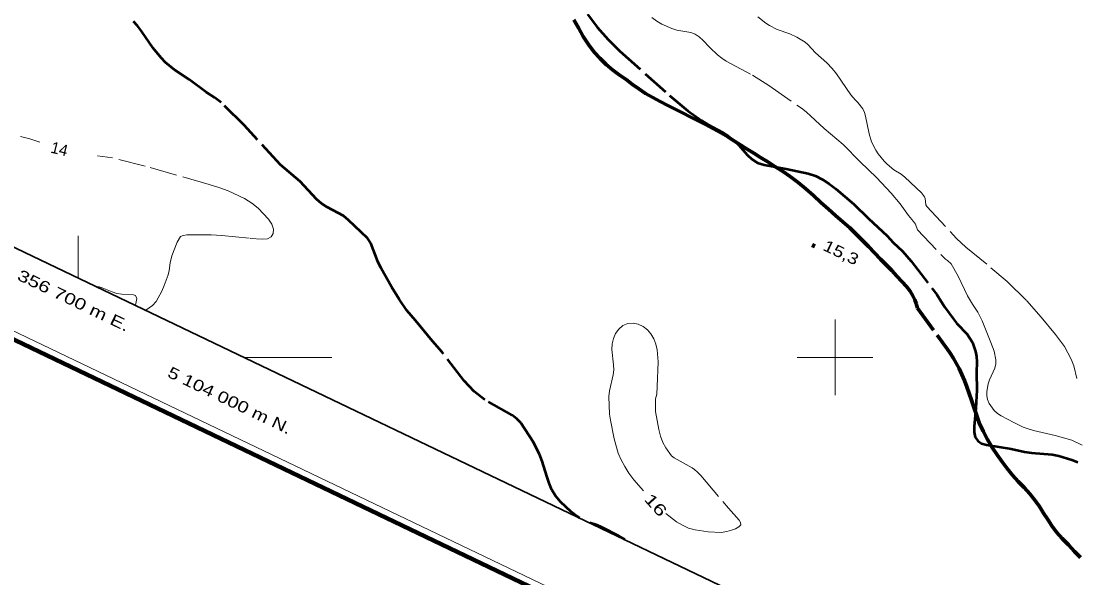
# Model space of a CAD drawing. Extents: x 355726 to 357533, y 5103782 to 5105258.
# Drawn here: x 356692.4 to 356831.8, y 5103970.9 to 5104044.4 of the extents above; entities that cross this region are included whole.
import ezdxf
from ezdxf.enums import TextEntityAlignment as Align

# ---------------------------------------------------------------- set-up
doc = ezdxf.new("R2010")
doc.units = 0
doc.header["$LTSCALE"] = 0.6
doc.linetypes.add('LONG_DASHED', pattern=[7.5, 6, -1.5])
for name, color, linetype, lineweight in [('1', 7, 'LONG_DASHED', 53), ('2', 7, 'LONG_DASHED', 13), ('22', 7, 'Continuous', 13), ('3', 7, 'Continuous', 140), ('60', 7, 'Continuous', 13), ('61', 7, 'Continuous', 13)]:
    doc.layers.add(name, color=color, linetype=linetype, lineweight=lineweight)

msp = doc.modelspace()

# ---------------------------------------------------------------- linework, layer by layer
at = {"layer": '1'}
for points in [[(356767.3, 5104045.33), (356768.57, 5104043.59), (356770.01, 5104041.99), (356771.56, 5104040.45), (356778.13, 5104034.59), (356780.54, 5104032.55), (356782.35, 5104031.29), (356783.27, 5104030.72), (356785.08, 5104029.72), (356785.9, 5104029.19), (356786.64, 5104028.62), (356787.29, 5104028.03), (356788.37, 5104026.75), (356788.98, 5104026.15), (356789.72, 5104025.69), (356790.63, 5104025.4), (356793.51, 5104024.91), (356796.44, 5104024.28), (356797.41, 5104023.97), (356798.33, 5104023.49), (356799.23, 5104022.9), (356800.09, 5104022.24), (356802.46, 5104020.21), (356804.41, 5104018.32), (356806.87, 5104016.03), (356807.67, 5104015.18), (356808.92, 5104014.01), (356810.05, 5104012.69), (356813.44, 5104008.28), (356814.45, 5104006.69), (356815.66, 5104005.01), (356816.08, 5104004.48), (356817.43, 5104003.05), (356818.16, 5104001.98), (356818.55, 5104000.76), (356818.66, 5104000.09), (356818.7, 5103999.42), (356818.66, 5103997.99), (356818.7, 5103995.65), (356818.61, 5103993.3), (356818.37, 5103990.88), (356818.35, 5103990.13), (356818.5, 5103989.47), (356818.84, 5103988.96), (356819.35, 5103988.63), (356820, 5103988.44), (356823.24, 5103987.9), (356825.02, 5103987.5), (356825.94, 5103987.37), (356828.67, 5103987.18), (356829.57, 5103986.99), (356831.27, 5103986.46), (356832.08, 5103986.16)], [(356766.22, 5103978.8), (356765.86, 5103979.01), (356765.14, 5103979.59), (356763.7, 5103980.94), (356763.06, 5103981.7), (356762.58, 5103982.49), (356762.21, 5103983.37), (356761.89, 5103984.3), (356761.31, 5103986.28), (356760.95, 5103987.21), (356760.12, 5103988.84), (356758.49, 5103991.33), (356757.95, 5103991.88), (356757.34, 5103992.37), (356753.72, 5103994.37), (356752.29, 5103995.5), (356750.97, 5103996.9), (356748.09, 5104000.67), (356746.8, 5104002.12), (356744.55, 5104004.87), (356743.41, 5104006.18), (356742.4, 5104007.67), (356741.38, 5104009.3), (356740.41, 5104011.01), (356739.96, 5104011.84), (356739.59, 5104012.67), (356738.65, 5104015.07), (356738.22, 5104015.75), (356735.69, 5104018.13), (356735.03, 5104018.67), (356732.87, 5104019.84), (356732.14, 5104020.33), (356731.48, 5104020.9), (356729.3, 5104023.21), (356726.72, 5104025.42), (356721.9, 5104030.67), (356718.86, 5104033.65), (356717.99, 5104034.3), (356716.9, 5104035.03), (356714.64, 5104036.71), (356712.71, 5104037.95), (356711.54, 5104038.95), (356710.96, 5104039.53), (356709.9, 5104040.84), (356708.37, 5104043.05), (356707.82, 5104043.78), (356707.3, 5104044.34)], [(356772.22, 5103975.93), (356771.38, 5103976.42), (356769.21, 5103977.55), (356768.55, 5103977.83), (356767.58, 5103978.15)]]:
    msp.add_lwpolyline(points, dxfattribs=at)
at = {"layer": '2'}
for points in [[(356775.79, 5104044.87), (356776.42, 5104044.38), (356777.1, 5104043.98), (356778.42, 5104043.41), (356779.08, 5104043.21)], [(356789.8, 5104044.98), (356790.83, 5104044.13), (356791.31, 5104043.8), (356792.33, 5104043.29), (356794.02, 5104042.73), (356794.92, 5104042.28), (356796.02, 5104041.61), (356796.37, 5104041.3), (356797.4, 5104040.21), (356798.92, 5104038.9), (356799.59, 5104038.16), (356800.16, 5104037.42), (356802.06, 5104034.66), (356802.63, 5104034.01), (356803, 5104033.67), (356803.66, 5104032.8), (356803.89, 5104032.32), (356804.03, 5104031.84), (356804.48, 5104029.51), (356804.81, 5104028.44), (356805.38, 5104027.36), (356805.7, 5104026.87), (356806.46, 5104025.91), (356806.86, 5104025.49), (356807.76, 5104024.78), (356808.72, 5104024.18), (356809.22, 5104023.8), (356811.42, 5104021.73), (356811.79, 5104021.21), (356811.89, 5104020.97), (356811.99, 5104020.13), (356812.12, 5104019.9), (356816.05, 5104015.7), (356817.26, 5104014.57), (356820.59, 5104011.84), (356822.71, 5104010), (356825.31, 5104007.46), (356827.22, 5104005.32), (356829.12, 5104003), (356830.3, 5104001.41), (356831.19, 5103999.75)], [(356779.08, 5104043.21), (356780.92, 5104042.91), (356781.49, 5104042.68), (356782.03, 5104042.34), (356782.53, 5104041.9), (356783.45, 5104040.92), (356784.46, 5104039.94), (356785.01, 5104039.5), (356785.62, 5104039.09), (356789.09, 5104037.25), (356791.24, 5104035.88), (356795.55, 5104032.9), (356796.18, 5104032.41), (356798.55, 5104030.24), (356801.04, 5104028.12), (356803.3, 5104025.8), (356805.47, 5104023.73), (356807.4, 5104021.66), (356808.59, 5104020.26), (356809.7, 5104018.71), (356810.37, 5104017.95), (356810.62, 5104017.57), (356810.88, 5104016.84), (356814.58, 5104012.96), (356814.84, 5104012.8), (356815.31, 5104012.36), (356816.24, 5104010.72), (356817.49, 5104008.13), (356818.13, 5104007.03), (356818.85, 5104005.95), (356819.44, 5104004.83), (356820.58, 5104001.95), (356820.99, 5104000.8), (356821.23, 5103999.69), (356821.23, 5103999.15), (356821.12, 5103998.59), (356820.38, 5103997.04), (356820.21, 5103996.51), (356820.03, 5103995.47), (356820.04, 5103994.92), (356820.15, 5103994.42), (356820.35, 5103993.91), (356821.03, 5103992.98), (356821.44, 5103992.59), (356821.92, 5103992.28), (356823.62, 5103991.38), (356824.86, 5103990.8), (356825.51, 5103990.55), (356826.19, 5103990.34), (356829.05, 5103989.66), (356831.26, 5103989.05), (356832.64, 5103988.41)], [(356694.91, 5104028.41), (356693.59, 5104028.84), (356692.38, 5104029.16)], [(356708.93, 5104006.22), (356709.82, 5104006.86), (356710.27, 5104007.38), (356711.02, 5104008.75), (356711.36, 5104009.5), (356711.86, 5104010.88), (356712.01, 5104011.46), (356712.16, 5104012.5), (356712.36, 5104013.41), (356713.06, 5104015.19), (356713.52, 5104015.94), (356713.86, 5104016.11), (356714.33, 5104016.18), (356717.56, 5104016.18), (356718.98, 5104016.11), (356722.71, 5104015.71), (356724.32, 5104015.61), (356725, 5104015.67), (356725.5, 5104015.93), (356725.76, 5104016.36), (356725.78, 5104016.94), (356725.56, 5104017.59), (356725.12, 5104018.24), (356723.75, 5104019.71), (356722.92, 5104020.38), (356721.98, 5104020.97), (356719.82, 5104021.99), (356718.58, 5104022.44), (356717.29, 5104022.84), (356708.83, 5104025.25), (356704.5, 5104026.36), (356702.56, 5104026.59)], [(356702.48, 5104009.3), (356702.74, 5104009.29), (356703.14, 5104009.19), (356704.47, 5104008.63), (356705.09, 5104008.44), (356705.76, 5104008.34), (356707.28, 5104008.24), (356707.55, 5104008.15), (356707.73, 5104007.76), (356707.55, 5104006.88)], [(356774.7, 5103982.37), (356773.42, 5103983.84), (356772.76, 5103984.71), (356772.2, 5103985.57), (356771.72, 5103986.46), (356771.33, 5103987.36), (356770.79, 5103989.23), (356770.3, 5103991.72), (356770.18, 5103992.5), (356770.12, 5103994.83), (356770.18, 5103995.59), (356770.66, 5103997.67), (356770.74, 5103998.34), (356770.73, 5103999.01), (356770.51, 5104001.05), (356770.56, 5104001.78), (356770.71, 5104002.5), (356770.99, 5104003.16), (356771.4, 5104003.74), (356771.94, 5104004.19), (356772.59, 5104004.45), (356773.31, 5104004.53), (356773.98, 5104004.4), (356774.62, 5104004.09), (356775.2, 5104003.65), (356775.66, 5104003.09), (356776.03, 5104002.45), (356776.3, 5104001.74), (356776.48, 5104000.98), (356776.6, 5103999.42), (356776.5, 5103996.13), (356776.42, 5103995.13), (356776.26, 5103994.51), (356776.27, 5103992.86), (356776.69, 5103990.46), (356776.94, 5103989.57), (356777.23, 5103988.76), (356777.61, 5103988.05), (356778.36, 5103987.01), (356778.72, 5103986.72), (356781.11, 5103985.4), (356781.43, 5103985.19), (356781.82, 5103984.84), (356782.26, 5103984.38), (356785.89, 5103980.08), (356787.3, 5103978.51), (356787.51, 5103978.2), (356787.53, 5103977.88), (356787.28, 5103977.63), (356786.84, 5103977.37), (356786.31, 5103977.16), (356785.67, 5103976.99), (356784.94, 5103976.88), (356783.24, 5103976.94), (356781.49, 5103977.21), (356780.62, 5103977.45), (356779.82, 5103977.82), (356779.04, 5103978.26), (356777.62, 5103979.38)], [(356831.19, 5103999.75), (356831.52, 5103998.86), (356831.95, 5103997.22)]]:
    msp.add_lwpolyline(points, dxfattribs=at)
at = {"layer": '22', "linetype": 'LONG_DASHED', "lineweight": 70}
for points in [[(356765.48, 5104044.59), (356766.09, 5104043.5), (356766.72, 5104042.37), (356767.4, 5104041.3), (356768.16, 5104040.3), (356768.94, 5104039.45), (356769.74, 5104038.68), (356770.57, 5104037.97), (356771.48, 5104037.3), (356772.37, 5104036.67), (356773.24, 5104036.03), (356774.08, 5104035.44), (356774.95, 5104034.84), (356775.9, 5104034.33), (356776.9, 5104033.78), (356777.91, 5104033.26), (356778.87, 5104032.76), (356779.85, 5104032.28), (356780.83, 5104031.78), (356781.83, 5104031.26), (356782.89, 5104030.74), (356783.93, 5104030.19), (356784.91, 5104029.65), (356785.84, 5104029.13), (356786.7, 5104028.55), (356787.52, 5104028.01), (356788.39, 5104027.51), (356789.26, 5104026.97), (356790.15, 5104026.4), (356791.09, 5104025.8), (356792.04, 5104025.2), (356793.05, 5104024.57), (356794.07, 5104023.86), (356795.1, 5104023.09), (356796.12, 5104022.26), (356797.12, 5104021.36), (356798.13, 5104020.46), (356799.11, 5104019.55), (356800.06, 5104018.71), (356801.01, 5104017.88), (356801.92, 5104017.08)], [(356801.92, 5104017.08), (356802.78, 5104016.26), (356803.62, 5104015.45), (356804.41, 5104014.63), (356805.2, 5104013.8), (356805.99, 5104012.97), (356806.76, 5104012.2), (356807.5, 5104011.47), (356808.17, 5104010.73), (356808.81, 5104010.03), (356809.42, 5104009.37), (356809.91, 5104008.73), (356810.25, 5104008.13), (356810.52, 5104007.59), (356810.7, 5104007.09), (356810.89, 5104006.51), (356813.48, 5104002.94), (356813.84, 5104002.46), (356814.08, 5104002.08), (356814.41, 5104001.63), (356814.8, 5104001.13), (356815.2, 5104000.55), (356815.6, 5103999.94), (356815.99, 5103999.25), (356816.38, 5103998.54), (356816.74, 5103997.75), (356817.08, 5103996.94), (356817.4, 5103996.09), (356817.71, 5103995.23), (356818.03, 5103994.34), (356818.32, 5103993.4), (356818.66, 5103992.42), (356819.05, 5103991.36), (356819.56, 5103990.25), (356820.12, 5103989.15), (356820.76, 5103988.11), (356821.4, 5103987.13), (356822.06, 5103986.21), (356822.72, 5103985.32), (356823.42, 5103984.46), (356824.16, 5103983.62), (356824.97, 5103982.8), (356825.71, 5103981.97), (356826.4, 5103981.13), (356826.99, 5103980.29), (356827.54, 5103979.44), (356828.08, 5103978.59), (356828.62, 5103977.75), (356829.26, 5103976.92), (356830.01, 5103976.08), (356830.82, 5103975.24), (356831.64, 5103974.38), (356832.41, 5103973.57)]]:
    msp.add_lwpolyline(points, dxfattribs=at)
at = {"layer": '3'}
msp.add_line((356796.97, 5104014.85), (356797.33, 5104014.68), dxfattribs=at)
at = {"layer": '60', "lineweight": 158}
msp.add_lwpolyline([(355725.74, 5104464.62), (357152.72, 5103781.6), (357532.66, 5104575.38), (356105.68, 5105258.4)], close=True, dxfattribs=at)
at = {"layer": '60'}
msp.add_lwpolyline([(355727.1, 5104465.08), (357152.24, 5103782.93), (357531.32, 5104574.91), (356106.18, 5105257.06)], close=True, dxfattribs=at)
at = {"layer": '60', "lineweight": 35}
msp.add_lwpolyline([(355740.43, 5104469.78), (356913.03, 5103908.53), (357283.46, 5104682.46), (356110.86, 5105243.71)], close=True, dxfattribs=at)
at = {"layer": '61'}
for p, q in [((356700, 5104010.49), (356700, 5104016.04)), ((356800, 5103995), (356800, 5104005)), ((356721.92, 5104000), (356733.51, 5104000)), ((356795, 5104000), (356805, 5104000))]:
    msp.add_line(p, q, dxfattribs=at)

# ---------------------------------------------------------------- texts
at = {"layer": '2'}
msp.add_text('14', height=1.5, rotation=346.104, dxfattribs=at).set_placement((356697.33, 5104026.79), align=Align.CENTER)
at = {"layer": '2', "width": 1.45}
msp.add_text('16', height=1.5, rotation=312.099, dxfattribs=at).set_placement((356775.74, 5103980), align=Align.CENTER)
at = {"layer": '3', "width": 1.25}
msp.add_text('15,3   ', height=1.5, rotation=334.423, dxfattribs=at).set_placement((356798.26, 5104014.22))
at = {"layer": '61'}
for s, width, p in [(' 356 700 m E.', 1.35, (356698.73, 5104006.99)), (' 5 104 000 m N.', 1.3, (356719.36, 5103993.8))]:
    msp.add_text(s, height=1.5, rotation=334.42, dxfattribs=dict(at, width=width)).set_placement(p, align=Align.CENTER)

doc.saveas('drawing.dxf')
